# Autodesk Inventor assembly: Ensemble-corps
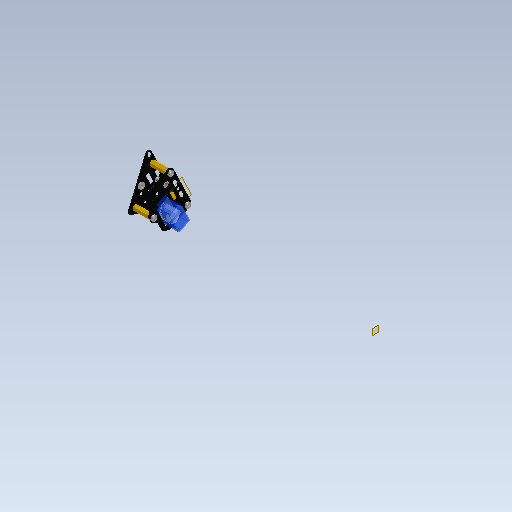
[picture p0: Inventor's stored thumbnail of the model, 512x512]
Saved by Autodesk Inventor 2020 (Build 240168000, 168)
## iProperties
Created: 2021-10
Part Number: Ensemble-corps
Document SubType Name: Assembly
Designer: bruno
Mass: 9.22633 g
Surface Area: 139.573 cm^2
Volume: 5.93462 cm^3
Density: 1.55466 g/cm^3
Author: bruno
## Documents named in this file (6)
- C:\Users\bruno\OneDrive\Bureau\Robot-Inventor\Robot-equilibrage\Ensemble-corps.iam
- C:\Users\bruno\OneDrive\Bureau\Robot-Inventor\Robot-equilibrage\Ensemble-support-servo.iam
- C:\Users\bruno\OneDrive\Bureau\Robot-Inventor\Robot-equilibrage\Servo\Servo.iam
- C:\Users\bruno\OneDrive\Bureau\Robot-Inventor\Robot-equilibrage\ecrou-hexa.ipt
- C:\Users\bruno\OneDrive\Bureau\Robot-Inventor\Robot-equilibrage\plaque-triangle.ipt
- C:\Users\bruno\Documents\Inventor\Content Center Files\R2020\fr-FR\ANSI B18.6.7M(01)\ANSI B18.6.7M - M3x0,5 x 5(5).ipt
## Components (12 placed, 5 different names)
1. Ensemble-support-servo:1 [sub-assembly] — Placage:1, Logement:1, Logement:2, Logement:3, Placage:5, Placage:6, Placage:7, Angle:1, Placage:10, Placage:13
2. Servo:1 [sub-assembly] — Placage:1, Placage:5
3. ecrou-hexa:1 — Logement:3, Placage:12, Placage:16
4. ecrou-hexa:2 — Logement:1, Placage:8, Placage:9, Placage:15
5. ecrou-hexa:3 — Logement:2, Placage:11, Placage:14
6. plaque-triangle:1 — Placage:8, Placage:9, Angle:1, Placage:17, Placage:18, Placage:19
7. Vis à tête tronconique à empreinte cruciforme - Type IA - Métrique M3x0,5 x 5:1 — Placage:6, Placage:7
8. Vis à tête tronconique à empreinte cruciforme - Type IA - Métrique M3x0,5 x 5:2 — Placage:10, Placage:11
9. Vis à tête tronconique à empreinte cruciforme - Type IA - Métrique M3x0,5 x 5:3 — Placage:12, Placage:13
10. Vis à tête tronconique à empreinte cruciforme - Type IA - Métrique M3x0,5 x 5:4 — Placage:14, Placage:19
11. Vis à tête tronconique à empreinte cruciforme - Type IA - Métrique M3x0,5 x 5:5 — Placage:15, Placage:18
12. Vis à tête tronconique à empreinte cruciforme - Type IA - Métrique M3x0,5 x 5:6 — Placage:16, Placage:17
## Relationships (20: Mate 16, Insert 3, Angle 1)
- Placage:1 [Mate]: Ensemble-support-servo:1 ↔ Servo:1
- Logement:1 [Insert]: Ensemble-support-servo:1 ↔ ecrou-hexa:2
- Logement:2 [Insert]: Ensemble-support-servo:1 ↔ ecrou-hexa:3
- Logement:3 [Insert]: Ensemble-support-servo:1 ↔ ecrou-hexa:1
- Placage:5 [Mate]: Ensemble-support-servo:1 ↔ Servo:1
- Placage:6 [Mate]: Ensemble-support-servo:1 ↔ Vis à tête tronconique à empreinte cruciforme - Type IA - Métrique M3x0,5 x 5:1
- Placage:7 [Mate]: Ensemble-support-servo:1 ↔ Vis à tête tronconique à empreinte cruciforme - Type IA - Métrique M3x0,5 x 5:1
- Placage:8 [Mate]: ecrou-hexa:2 ↔ plaque-triangle:1
- Placage:9 [Mate]: ecrou-hexa:2 ↔ plaque-triangle:1
- Angle:1: Ensemble-support-servo:1 ↔ plaque-triangle:1
- Placage:10 [Mate]: Ensemble-support-servo:1 ↔ Vis à tête tronconique à empreinte cruciforme - Type IA - Métrique M3x0,5 x 5:2
- Placage:11 [Mate]: ecrou-hexa:3 ↔ Vis à tête tronconique à empreinte cruciforme - Type IA - Métrique M3x0,5 x 5:2
- Placage:12 [Mate]: ecrou-hexa:1 ↔ Vis à tête tronconique à empreinte cruciforme - Type IA - Métrique M3x0,5 x 5:3
- Placage:13 [Mate]: Ensemble-support-servo:1 ↔ Vis à tête tronconique à empreinte cruciforme - Type IA - Métrique M3x0,5 x 5:3
- Placage:14 [Mate]: ecrou-hexa:3 ↔ Vis à tête tronconique à empreinte cruciforme - Type IA - Métrique M3x0,5 x 5:4
- Placage:15 [Mate]: ecrou-hexa:2 ↔ Vis à tête tronconique à empreinte cruciforme - Type IA - Métrique M3x0,5 x 5:5
- Placage:16 [Mate]: ecrou-hexa:1 ↔ Vis à tête tronconique à empreinte cruciforme - Type IA - Métrique M3x0,5 x 5:6
- Placage:17 [Mate]: plaque-triangle:1 ↔ Vis à tête tronconique à empreinte cruciforme - Type IA - Métrique M3x0,5 x 5:6
- Placage:18 [Mate]: plaque-triangle:1 ↔ Vis à tête tronconique à empreinte cruciforme - Type IA - Métrique M3x0,5 x 5:5
- Placage:19 [Mate]: plaque-triangle:1 ↔ Vis à tête tronconique à empreinte cruciforme - Type IA - Métrique M3x0,5 x 5:4
